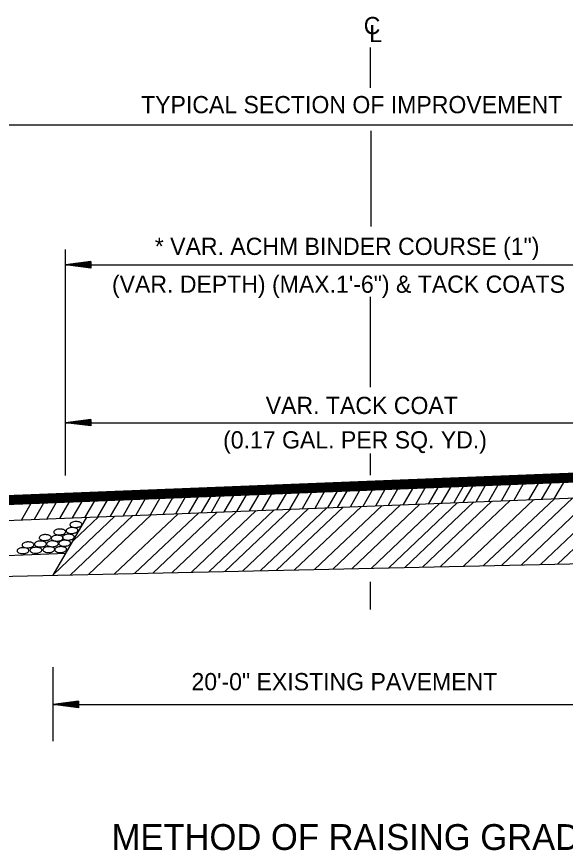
# Model space of a CAD drawing. Extents: x 836 to 5683, y -463 to 1545.
# Drawn here: x 4814.3 to 5005.3, y 632.2 to 922.6 of the extents above; entities that cross this region are included whole.
import ezdxf

# ---------------------------------------------------------------- set-up
doc = ezdxf.new("R2010")
doc.units = 0
for name, color, linetype in [('r061377_05A_SD_MAIN_002 - R_Annotation', 7, 'Continuous'), ('R_Grid', 7, 'Continuous'), ('R_No Plot', 7, 'Continuous')]:
    doc.layers.add(name, color=color, linetype=linetype)

msp = doc.modelspace()

# ---------------------------------------------------------------- linework, layer by layer
at = {"layer": 'R_Grid'}
for p, q in [((4657.04, 884.96), (5217.98, 884.96)), ((4831.26, 762.75), (4831.26, 841.56)), ((4840.08, 837.29), (4831.26, 836.14)), ((4840.09, 836.6), (4834.78, 836.59)), ((4840.08, 836.83), (4836.56, 836.83)), ((4840.08, 837.06), (4838.35, 837.05)), ((4840.08, 837.29), (4840.09, 835)), ((4831.26, 836.14), (5042.87, 836.14)), ((4831.26, 836.14), (4840.08, 836.14)), ((4840.09, 835), (4831.26, 836.14)), ((4840.08, 836.37), (4833.05, 836.37)), ((4840.09, 835.92), (4833.05, 835.91)), ((4840.09, 835.68), (4834.78, 835.68)), ((4840.09, 835.45), (4836.57, 835.45)), ((4840.09, 835.22), (4838.35, 835.22)), ((4840.08, 782.32), (4831.26, 781.17)), ((4840.08, 782.32), (4831.26, 781.17)), ((4840.08, 781.4), (4833.05, 781.4)), ((4840.08, 781.4), (4833.05, 781.4)), ((4840.09, 781.63), (4834.78, 781.63)), ((4840.09, 781.63), (4834.78, 781.63)), ((4840.08, 781.86), (4836.56, 781.86)), ((4840.08, 781.86), (4836.56, 781.86)), ((4840.08, 782.09), (4838.35, 782.09)), ((4840.08, 782.09), (4838.35, 782.09)), ((4840.08, 782.32), (4840.09, 780.03)), ((4840.08, 782.32), (4840.09, 780.03)), ((4831.26, 781.17), (5042.87, 781.17)), ((4831.26, 781.17), (4840.08, 781.17)), ((4840.09, 780.03), (4831.26, 781.17)), ((4831.26, 781.17), (4840.08, 781.17)), ((4840.09, 780.03), (4831.26, 781.17)), ((4840.09, 780.95), (4833.05, 780.95)), ((4840.09, 780.95), (4833.05, 780.95)), ((4840.09, 780.72), (4834.78, 780.72)), ((4840.09, 780.72), (4834.78, 780.72)), ((4840.09, 780.49), (4836.57, 780.48)), ((4840.09, 780.49), (4836.57, 780.48)), ((4840.09, 780.26), (4838.35, 780.25)), ((4840.09, 780.26), (4838.35, 780.25)), ((4827, 670.19), (4827, 695.94)), ((4835.82, 684.17), (4827, 683.02)), ((4827, 683.02), (5047.2, 683.02)), ((4827, 683.02), (4835.82, 683.02)), ((4835.82, 681.88), (4827, 683.02)), ((4835.82, 683.25), (4828.79, 683.25)), ((4835.83, 682.8), (4828.79, 682.8)), ((4835.83, 683.48), (4830.52, 683.47)), ((4835.83, 682.56), (4830.52, 682.57)), ((4835.82, 683.71), (4832.3, 683.71)), ((4835.82, 683.94), (4834.09, 683.93)), ((4835.82, 684.17), (4835.82, 681.88)), ((4835.83, 682.34), (4832.31, 682.33)), ((4835.83, 682.11), (4834.09, 682.1))]:
    msp.add_line(p, q, dxfattribs=at)
at = {"layer": 'R_No Plot'}
for p, q in [((4937.4, 897.86), (4937.4, 911.83)), ((4937.62, 856.05), (4937.62, 882.9)), ((4937.62, 849.55), (4937.62, 856.05)), ((4937.4, 793.53), (4937.4, 825.04)), ((4654.18, 748.2), (5220.52, 770.79)), ((4654.91, 748.58), (5219.89, 771.11)), ((4655.64, 748.93), (5219.26, 771.42)), ((4656.39, 749.31), (5218.6, 771.74)), ((4657.04, 749.63), (5218, 772.04)), ((4937.4, 762.91), (4937.4, 770.47)), ((4740.65, 751.28), (5133.92, 766.98)), ((4739.75, 749.9), (5134.84, 765.62)), ((4739.99, 750.23), (5134.62, 765.96)), ((4740.2, 750.59), (5134.39, 766.29)), ((4740.41, 750.93), (5133.92, 766.6)), ((4736.14, 744.13), (5138.6, 760.14)), ((4952.01, 758.23), (4948.68, 752.48)), ((4956.4, 758.32), (4953.15, 752.66)), ((4960.85, 758.6), (4957.57, 752.84)), ((4965.29, 758.76), (4961.98, 753.04)), ((4969.71, 758.93), (4966.4, 753.19)), ((4972.96, 759.1), (4969.64, 753.33)), ((4977.41, 759.29), (4974.07, 753.51)), ((4981.8, 759.43), (4978.51, 753.72)), ((4986.22, 759.61), (4982.92, 753.87)), ((4990.64, 759.82), (4987.34, 754.04)), ((4995.78, 759.99), (4992.47, 754.25)), ((5000.17, 760.07), (4996.91, 754.44)), ((5004.62, 760.36), (5001.32, 754.6)), ((4872.97, 755.22), (4869.68, 749.48)), ((4877.4, 755.41), (4874.11, 749.66)), ((4881.81, 755.6), (4878.51, 749.86)), ((4885.25, 755.64), (4881.95, 749.92)), ((4889.72, 755.82), (4886.39, 750.06)), ((4894.11, 755.99), (4890.8, 750.25)), ((4898.54, 756.18), (4895.23, 750.43)), ((4902.95, 756.35), (4899.65, 750.6)), ((4908.06, 756.55), (4904.74, 750.79)), ((4912.45, 756.65), (4909.2, 750.99)), ((4916.95, 756.9), (4913.62, 751.18)), ((4921.36, 757.09), (4918.05, 751.32)), ((4925.78, 757.26), (4922.47, 751.51)), ((4929.19, 757.33), (4925.89, 751.59)), ((4933.63, 757.49), (4930.32, 751.77)), ((4938.04, 757.67), (4934.73, 751.92)), ((4942.45, 757.88), (4939.16, 752.1)), ((4946.88, 758.04), (4943.59, 752.3)), ((4989.96, 731.66), (5014.67, 755.22)), ((4996.64, 731.81), (5021.51, 755.49)), ((5002.67, 731.95), (5027.68, 755.73)), ((4819.19, 753.06), (4815.88, 747.29)), ((4823.57, 753.14), (4820.32, 747.47)), ((4828.03, 753.38), (4824.73, 747.64)), ((4832.48, 753.58), (4829.17, 747.84)), ((4836.89, 753.75), (4833.59, 748.02)), ((4841.31, 753.96), (4837.99, 748.21)), ((4845.75, 754.13), (4842.45, 748.39)), ((4850.15, 754.35), (4846.86, 748.59)), ((4854.58, 754.5), (4851.29, 748.75)), ((4858.98, 754.67), (4855.69, 748.92)), ((4864.11, 754.89), (4860.82, 749.13)), ((4868.52, 754.98), (4865.26, 749.31)), ((4917.92, 730.04), (4941.46, 752.31)), ((4924.27, 730.17), (4947.86, 752.56)), ((4931.08, 730.34), (4954.65, 752.82)), ((4937.77, 730.48), (4961.53, 753.12)), ((4943.8, 730.63), (4967.68, 753.33)), ((4949.36, 730.74), (4973.44, 753.58)), ((4955.54, 730.88), (4979.72, 753.82)), ((4961.83, 731.03), (4986.07, 754.07)), ((4969.86, 731.22), (4994.27, 754.42)), ((4976.84, 731.37), (5001.45, 754.68)), ((4983.18, 731.51), (5007.86, 754.97)), ((4848.32, 728.49), (4870.44, 749.46)), ((4855.3, 728.62), (4877.62, 749.76)), ((4861.62, 728.76), (4884.01, 749.99)), ((4868.43, 728.92), (4890.84, 750.28)), ((4875.11, 729.09), (4897.67, 750.58)), ((4881.14, 729.21), (4903.85, 750.79)), ((4886.73, 729.33), (4909.61, 751.04)), ((4892.9, 729.47), (4915.88, 751.28)), ((4899.2, 729.63), (4922.23, 751.54)), ((4904.72, 729.75), (4927.97, 751.78)), ((4910.95, 729.88), (4934.29, 751.99)), ((4827, 728), (4838.64, 748.21)), ((4827.24, 728.41), (4848.44, 748.61)), ((4832.89, 728.1), (4854.74, 748.83)), ((4833.91, 740), (4842.69, 748.36)), ((4839.22, 728.26), (4861.09, 749.1)), ((4611.68, 726.96), (4831.44, 735.71)), ((4782.86, 727.01), (5091.21, 733.94)), ((4937.4, 716.14), (4937.4, 725.75))]:
    msp.add_line(p, q, dxfattribs=at)
for points in [[(4834.86, 744.7), (4834.12, 744.71), (4833.32, 744.99), (4832.86, 745.39), (4832.81, 745.62), (4833, 746.11), (4833.27, 746.31), (4833.74, 746.54), (4834.45, 746.71), (4834.79, 746.74), (4835.35, 746.69), (4835.96, 746.6), (4836.42, 746.44), (4836.86, 746.06), (4836.94, 745.82), (4836.81, 745.4), (4836.48, 745.11), (4836.15, 744.9), (4835.64, 744.78), (4835.33, 744.71), (4834.86, 744.7)], [(4829.25, 742.08), (4828.51, 742.09), (4827.71, 742.37), (4827.24, 742.77), (4827.19, 743), (4827.38, 743.49), (4827.66, 743.69), (4828.13, 743.92), (4828.84, 744.09), (4829.18, 744.12), (4829.74, 744.07), (4830.34, 743.98), (4830.81, 743.82), (4831.25, 743.44), (4831.33, 743.2), (4831.2, 742.79), (4830.87, 742.49), (4830.53, 742.28), (4830.03, 742.16), (4829.71, 742.09), (4829.25, 742.08)], [(4833.51, 742.6), (4832.78, 742.62), (4831.98, 742.9), (4831.51, 743.3), (4831.46, 743.52), (4831.65, 744.01), (4831.93, 744.22), (4832.39, 744.45), (4833.11, 744.61), (4833.45, 744.65), (4834.01, 744.6), (4834.61, 744.51), (4835.08, 744.34), (4835.51, 743.97), (4835.59, 743.72), (4835.46, 743.31), (4835.13, 743.01), (4834.8, 742.81), (4834.3, 742.69), (4833.98, 742.62), (4833.51, 742.6)], [(4824.16, 740.13), (4823.42, 740.15), (4822.62, 740.43), (4822.15, 740.83), (4822.1, 741.05), (4822.3, 741.54), (4822.57, 741.75), (4823.04, 741.98), (4823.75, 742.14), (4824.09, 742.18), (4824.65, 742.13), (4825.25, 742.04), (4825.72, 741.87), (4826.16, 741.5), (4826.24, 741.25), (4826.11, 740.84), (4825.78, 740.54), (4825.44, 740.34), (4824.94, 740.22), (4824.62, 740.15), (4824.16, 740.13)], [(4828.35, 739.91), (4827.61, 739.92), (4826.81, 740.2), (4826.34, 740.6), (4826.3, 740.83), (4826.49, 741.32), (4826.76, 741.52), (4827.23, 741.75), (4827.94, 741.92), (4828.28, 741.95), (4828.84, 741.9), (4829.44, 741.81), (4829.91, 741.65), (4830.35, 741.27), (4830.43, 741.03), (4830.3, 740.62), (4829.97, 740.32), (4829.64, 740.11), (4829.13, 739.99), (4828.81, 739.92), (4828.35, 739.91)], [(4832.24, 740.28), (4831.5, 740.3), (4830.7, 740.58), (4830.24, 740.98), (4830.19, 741.2), (4830.38, 741.69), (4830.65, 741.9), (4831.12, 742.13), (4831.84, 742.29), (4832.18, 742.33), (4832.73, 742.28), (4833.34, 742.19), (4833.8, 742.02), (4834.24, 741.65), (4834.32, 741.4), (4834.19, 740.99), (4833.86, 740.69), (4833.53, 740.49), (4833.02, 740.37), (4832.71, 740.3), (4832.24, 740.28)], [(4818.17, 737.59), (4817.43, 737.6), (4816.63, 737.88), (4816.17, 738.28), (4816.12, 738.51), (4816.31, 739), (4816.58, 739.2), (4817.05, 739.43), (4817.77, 739.6), (4818.11, 739.63), (4818.67, 739.58), (4819.27, 739.49), (4819.73, 739.33), (4820.17, 738.95), (4820.25, 738.71), (4820.12, 738.3), (4819.79, 738), (4819.46, 737.79), (4818.96, 737.67), (4818.64, 737.6), (4818.17, 737.59)], [(4820.94, 735.72), (4820.2, 735.73), (4819.4, 736.01), (4818.94, 736.41), (4818.89, 736.64), (4819.08, 737.12), (4819.35, 737.33), (4819.82, 737.56), (4820.54, 737.73), (4820.88, 737.76), (4821.43, 737.71), (4822.04, 737.62), (4822.5, 737.46), (4822.94, 737.08), (4823.02, 736.83), (4822.89, 736.42), (4822.56, 736.13), (4822.23, 735.92), (4821.72, 735.8), (4821.41, 735.73), (4820.94, 735.72)], [(4822.51, 737.89), (4821.77, 737.9), (4820.97, 738.18), (4820.51, 738.58), (4820.46, 738.81), (4820.65, 739.3), (4820.93, 739.5), (4821.39, 739.73), (4822.11, 739.9), (4822.45, 739.93), (4823.01, 739.88), (4823.61, 739.79), (4824.07, 739.63), (4824.51, 739.25), (4824.59, 739), (4824.46, 738.59), (4824.13, 738.3), (4823.8, 738.09), (4823.3, 737.97), (4822.98, 737.9), (4822.51, 737.89)], [(4825.43, 735.94), (4824.69, 735.96), (4823.89, 736.24), (4823.43, 736.63), (4823.38, 736.86), (4823.57, 737.35), (4823.84, 737.55), (4824.31, 737.79), (4825.03, 737.95), (4825.37, 737.99), (4825.92, 737.94), (4826.53, 737.84), (4826.99, 737.68), (4827.43, 737.31), (4827.51, 737.06), (4827.38, 736.65), (4827.05, 736.35), (4826.72, 736.15), (4826.21, 736.03), (4825.9, 735.96), (4825.43, 735.94)], [(4826.7, 737.96), (4825.97, 737.98), (4825.17, 738.26), (4824.7, 738.66), (4824.65, 738.88), (4824.84, 739.37), (4825.12, 739.58), (4825.58, 739.81), (4826.3, 739.97), (4826.64, 740.01), (4827.2, 739.96), (4827.8, 739.87), (4828.27, 739.7), (4828.7, 739.33), (4828.78, 739.08), (4828.65, 738.67), (4828.32, 738.37), (4827.99, 738.17), (4827.49, 738.05), (4827.17, 737.98), (4826.7, 737.96)], [(4829.54, 735.94), (4828.81, 735.96), (4828.01, 736.24), (4827.54, 736.63), (4827.49, 736.86), (4827.68, 737.35), (4827.96, 737.55), (4828.43, 737.79), (4829.14, 737.95), (4829.48, 737.99), (4830.04, 737.94), (4830.64, 737.84), (4831.11, 737.68), (4831.55, 737.31), (4831.63, 737.06), (4831.5, 736.65), (4831.17, 736.35), (4830.83, 736.15), (4830.33, 736.03), (4830.01, 735.96), (4829.54, 735.94)], [(4830.97, 738.19), (4830.23, 738.2), (4829.43, 738.48), (4828.96, 738.88), (4828.91, 739.11), (4829.11, 739.59), (4829.38, 739.8), (4829.85, 740.03), (4830.56, 740.2), (4830.9, 740.23), (4831.46, 740.18), (4832.06, 740.09), (4832.53, 739.93), (4832.97, 739.55), (4833.05, 739.3), (4832.92, 738.89), (4832.59, 738.6), (4832.25, 738.39), (4831.75, 738.27), (4831.43, 738.2), (4830.97, 738.19)], [(4816.45, 735.57), (4815.71, 735.58), (4814.91, 735.86), (4814.45, 736.26), (4814.4, 736.49), (4814.59, 736.98), (4814.86, 737.18), (4815.33, 737.41), (4816.05, 737.58), (4816.38, 737.61), (4816.94, 737.56), (4817.55, 737.47), (4818.01, 737.31), (4818.45, 736.93), (4818.53, 736.69), (4818.4, 736.27), (4818.07, 735.98), (4817.74, 735.77), (4817.23, 735.65), (4816.92, 735.58), (4816.45, 735.57)]]:
    msp.add_spline(points, degree=3, dxfattribs=at)

# ---------------------------------------------------------------- texts
at = {"layer": 'r061377_05A_SD_MAIN_002 - R_Annotation'}
msp.add_text(' METHOD OF RAISING GRADE ', height=9, dxfattribs=at).set_placement((4843.94, 632.31))
at = {"layer": 'R_No Plot'}
for s, p in [('C', (4935.08, 916.53)), ('L', (4936.98, 913.77)), ('TYPICAL SECTION OF IMPROVEMENT', (4857.57, 888.98)), ('* VAR. ACHM BINDER COURSE (1")', (4862.34, 839.61)), ('(VAR. DEPTH) (MAX.1\'-6") & TACK COATS', (4847.43, 826.43)), ('VAR. TACK COAT', (4900.97, 784.19)), ('(0.17 GAL. PER SQ. YD.)', (4886.12, 772.19)), ('20\'-0" EXISTING PAVEMENT', (4875.11, 687.95))]:
    msp.add_text(s, height=6, dxfattribs=at).set_placement(p)

doc.saveas('drawing.dxf')
